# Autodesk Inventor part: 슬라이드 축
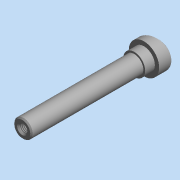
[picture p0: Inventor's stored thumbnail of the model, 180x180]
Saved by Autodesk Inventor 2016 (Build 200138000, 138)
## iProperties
Created: 2015-11
Part Number: 슬라이드 축
Document SubType Name: 모델링
Designer: mdu
Mass: 174.309 g
Surface Area: 67.586 cm^2
Volume: 21.5729 cm^3
Density: 8.08 g/cm^3
Material: 스테인리스강
Appearance: 기본값
변환 표준: STEP AP214IS
파일 이름: C:\Users\SeoGD\Desktop\?쒗뿕\異?stp
전처리기: Build: 253, Release: 2010 SP1 - Date: Wed 07/29/2009
전송 단위: 밀리미터
불확실성: 0.01
Author: mdu
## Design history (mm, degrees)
sketch "스케치1"
  geometry: L1 (0, 100)-(7.5, 100); L2 (7.5, 100)-(7.5, 0); L3 (7.5, 0)-(12.5, 0); L4 (12.5, 0)-(12.5, -17); L5 (12.5, -17)-(0, -17); L6 (0, -17)-(0, 100); 1 further point
  constraints: 12 end point, 2 parallel, 2 point on line, 1 perpendicular, 1 vertical
  dimensions: "d0" = 100 distance from line of L1 point (0, 0); "d1" = 15 diameter of L2 L6; "d2" = 25 diameter of L4 L6; "d3" = 17 distance of L3.end L4.end
revolve "회전1" sketch "스케치1" stored, may be unused: angle "d4" = 90 deg
sketch "스케치2"
  geometry: L1 (12.5, 0)-(12.5, -17) reference; L2 (-12.5, -17)-(12.5, -17) reference; L3 (-12.5, 0)-(-12.5, -17) reference; L4 (12.5, -5)-(-12.5, -11.699); L5 (-12.5, 0)-(12.5, 0) reference; 1 further point
  constraints: 2 end point, 2 point on line
  dimensions: "d5" = 75 deg angle of L1 L4; "d6" = 5 distance from line of L4.start L5
extrude "돌출1" cut sketch "스케치2" stored distance "d7" = 10; taper "d8" = 0 deg
chamfer "모따기1" distance "d9" = 1; stored, may be unused: second distance "d10" = 2, angle "d11" = 45 deg
fillet "모깎기1" dims "d12" = 0.5
hole "구멍1" diameter "d15" = 6.647; stored, may be unused: countersink angle "d19" = 90 deg, drill point angle "d21" = 118 deg; dims "d13" = 10, "d14" = 10, "d16" = 17, "d17" = 4, "d18" = 2, "d20" = 20
chamfer "모따기2" distance "d22" = 1; stored, may be unused: second distance "d23" = 2, angle "d24" = 45 deg
sketch "스케치3"
  geometry: C1 r 9 at (0, 0); 1 further point
  constraints: 1 centre point, 1 coincident
  dimensions: "d25" = 18 diameter of C1
extrude "돌출2" join sketch "스케치3" distance "d26" = 8; taper "d27" = 0 deg
node "솔리드1"
node "솔리드 본체"
node "곡면 본체"
node "솔리드2"
